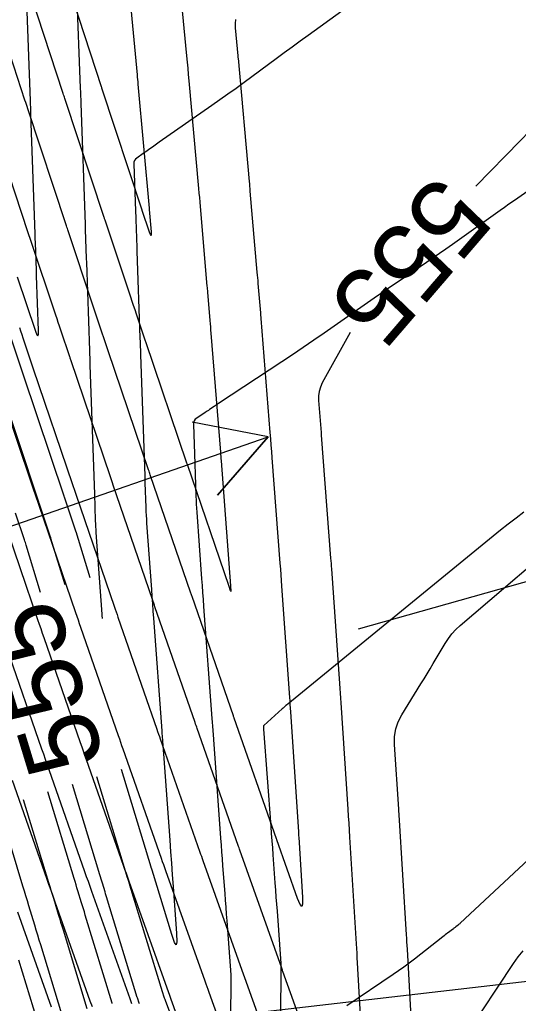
# Model space of a CAD drawing. Extents: x 954385 to 988206, y 1868364 to 1924553.
# Drawn here: x 957830.8 to 957869.5, y 1919489.8 to 1919566.3 of the extents above; entities that cross this region are included whole.
import ezdxf

# ---------------------------------------------------------------- set-up
doc = ezdxf.new("R2010")
doc.units = 0
doc.layers.add('1', color=7, linetype='Continuous')
doc.layers.add('Slopes', color=7, linetype='Continuous')

msp = doc.modelspace()

# ---------------------------------------------------------------- linework, layer by layer
for points in [[(957837.226, 1919519.732), (957837.226, 1919519.741), (957837.209, 1919519.965), (957837.202, 1919520.066), (957836.741, 1919526.42), (957836.726, 1919526.647), (957836.713, 1919526.874), (957836.702, 1919527.101), (957836.694, 1919527.328), (957836.66, 1919528.411), (957836.656, 1919528.551), (957836.652, 1919528.692), (957836.647, 1919528.833), (957836.643, 1919528.973), (957836.626, 1919529.536), (957836.621, 1919529.676), (957836.617, 1919529.817), (957836.612, 1919529.958), (957836.607, 1919530.098), (957836.28, 1919539.427), (957836.27, 1919539.713), (957836.26, 1919539.998), (957836.25, 1919540.284), (957836.24, 1919540.569), (957835.999, 1919547.422), (957835.989, 1919547.727), (957835.91, 1919549.962), (957835.895, 1919550.396), (957835.567, 1919559.766), (957835.557, 1919560.063), (957835.546, 1919560.36), (957835.535, 1919560.657), (957835.524, 1919560.954), (957835.235, 1919568.503)], [(957830.606, 1919546.301), (957832.022, 1919542.079), (957832.135, 1919541.786), (957832.212, 1919541.696), (957832.252, 1919541.808), (957832.256, 1919542.121), (957832.107, 1919546.373), (957832.091, 1919546.824), (957832.018, 1919548.928), (957832.005, 1919549.279), (957831.993, 1919549.629), (957831.667, 1919558.952), (957831.658, 1919559.206), (957831.649, 1919559.46), (957831.64, 1919559.714), (957831.63, 1919559.968), (957831.337, 1919567.616)], [(957855.832, 1919566.952), (957853.223, 1919565.063), (957852.597, 1919564.609), (957851.972, 1919564.153), (957851.348, 1919563.697), (957850.725, 1919563.239), (957848.233, 1919561.405), (957847.609, 1919560.948), (957846.981, 1919560.496), (957846.351, 1919560.048), (957845.718, 1919559.604), (957841.623, 1919556.752), (957841.52, 1919556.68), (957841.417, 1919556.608), (957841.315, 1919556.536), (957841.212, 1919556.463), (957840.804, 1919556.17), (957840.701, 1919556.097), (957840.599, 1919556.025), (957840.496, 1919555.953), (957840.393, 1919555.881), (957839.887, 1919555.53), (957839.784, 1919555.439), (957839.712, 1919555.334), (957839.671, 1919555.213), (957839.66, 1919555.076), (957839.789, 1919551.409), (957839.806, 1919550.915), (957839.812, 1919550.751), (957839.888, 1919548.563), (957839.897, 1919548.299), (957840.134, 1919541.543), (957840.146, 1919541.221), (957840.157, 1919540.899), (957840.168, 1919540.577), (957840.179, 1919540.254), (957840.511, 1919530.802), (957840.513, 1919530.76), (957840.514, 1919530.718), (957840.516, 1919530.675), (957840.517, 1919530.633), (957840.522, 1919530.464), (957840.525, 1919530.379), (957840.528, 1919530.294), (957840.591, 1919528.355), (957840.603, 1919528.053), (957840.617, 1919527.751), (957840.634, 1919527.45), (957840.655, 1919527.148), (957841.029, 1919521.992), (957841.069, 1919521.434), (957841.11, 1919520.876), (957841.15, 1919520.318), (957841.191, 1919519.76), (957841.83, 1919511.001), (957841.845, 1919510.792), (957841.86, 1919510.583), (957841.94, 1919509.494), (957841.959, 1919509.225), (957842.451, 1919502.509), (957842.517, 1919501.609), (957842.583, 1919500.708), (957842.65, 1919499.808), (957842.716, 1919498.908), (957842.986, 1919495.252), (957843.01, 1919494.593), (957842.955, 1919494.361), (957842.82, 1919494.557), (957842.605, 1919495.181), (957841.085, 1919500.166), (957841.062, 1919500.243), (957841.021, 1919500.378), (957841.015, 1919500.397), (957838.7, 1919508.002)], [(957870.876, 1919553.371), (957869.505, 1919552.416), (957869.163, 1919552.176), (957868.821, 1919551.936), (957868.48, 1919551.695), (957868.139, 1919551.454), (957864.419, 1919548.807), (957863.917, 1919548.452), (957863.413, 1919548.1), (957862.908, 1919547.75), (957862.4, 1919547.404), (957860.364, 1919546.023), (957859.856, 1919545.678), (957859.349, 1919545.33), (957858.842, 1919544.981), (957858.337, 1919544.63), (957854.457, 1919541.925), (957853.64, 1919541.359), (957852.82, 1919540.799), (957851.996, 1919540.244), (957851.169, 1919539.694), (957846.243, 1919536.442), (957846.156, 1919536.384), (957846.068, 1919536.326), (957845.981, 1919536.268), (957845.894, 1919536.209), (957845.547, 1919535.973), (957845.46, 1919535.915), (957845.373, 1919535.856), (957845.286, 1919535.798), (957845.198, 1919535.74), (957844.559, 1919535.319), (957844.441, 1919535.221), (957844.359, 1919535.104), (957844.311, 1919534.969), (957844.299, 1919534.816), (957844.407, 1919531.751), (957844.409, 1919531.685), (957844.412, 1919531.618), (957844.414, 1919531.552), (957844.416, 1919531.486), (957844.425, 1919531.221), (957844.427, 1919531.155), (957844.429, 1919531.089), (957844.431, 1919531.022), (957844.434, 1919530.956), (957844.492, 1919529.243), (957844.504, 1919528.936), (957844.519, 1919528.629), (957844.537, 1919528.321), (957844.558, 1919528.014), (957844.934, 1919522.826), (957844.973, 1919522.289), (957845.012, 1919521.753), (957845.051, 1919521.217), (957845.09, 1919520.681), (957845.725, 1919511.97), (957845.747, 1919511.669), (957845.769, 1919511.368), (957845.844, 1919510.35), (957845.846, 1919510.322), (957846.407, 1919502.658), (957846.447, 1919502.122), (957846.486, 1919501.585), (957846.525, 1919501.049), (957846.565, 1919500.513), (957846.723, 1919498.369), (957846.762, 1919497.833), (957846.802, 1919497.297), (957846.841, 1919496.761), (957846.881, 1919496.225), (957847.19, 1919492.023), (957847.193, 1919491.972), (957847.195, 1919491.922), (957847.197, 1919491.871), (957847.197, 1919491.821), (957847.196, 1919491.384), (957847.196, 1919491.339), (957847.195, 1919491.295), (957847.104, 1919482.111)], [(957828.862, 1919545.242), (957830.984, 1919538.91), (957831.066, 1919538.667), (957834.213, 1919529.278), (957834.223, 1919529.247), (957834.239, 1919529.201), (957834.244, 1919529.186), (957835.128, 1919526.546), (957835.133, 1919526.533), (957835.137, 1919526.521), (957835.141, 1919526.508), (957835.145, 1919526.495), (957836.233, 1919522.931)], [(957834.325, 1919522.35), (957833.223, 1919525.96), (957833.204, 1919526.021), (957833.185, 1919526.082), (957833.165, 1919526.142), (957833.145, 1919526.203), (957832.359, 1919528.549), (957832.35, 1919528.576), (957832.341, 1919528.602), (957832.332, 1919528.628), (957832.323, 1919528.655), (957832.287, 1919528.76), (957832.278, 1919528.786), (957832.269, 1919528.812), (957832.26, 1919528.839), (957832.252, 1919528.865), (957829.163, 1919538.081)], [(957832.417, 1919521.768), (957831.301, 1919525.426), (957831.267, 1919525.534), (957831.233, 1919525.643), (957831.198, 1919525.751), (957831.162, 1919525.859), (957830.474, 1919527.912)], [(957869.982, 1919527.989), (957869.373, 1919527.536), (957868.77, 1919527.075), (957868.174, 1919526.606), (957867.583, 1919526.13), (957851.628, 1919513.085), (957851.612, 1919513.072), (957851.596, 1919513.059), (957851.58, 1919513.045), (957851.563, 1919513.032), (957851.474, 1919512.961), (957851.466, 1919512.954), (957851.458, 1919512.947), (957851.426, 1919512.919), (957851.264, 1919512.772), (957851.191, 1919512.706), (957849.765, 1919511.417), (957849.752, 1919511.402), (957849.743, 1919511.386), (957849.738, 1919511.369), (957849.738, 1919511.349), (957849.753, 1919511.14), (957850.308, 1919503.558), (957850.348, 1919503.01), (957850.388, 1919502.463), (957850.429, 1919501.915), (957850.469, 1919501.367), (957850.63, 1919499.177), (957850.67, 1919498.629), (957850.71, 1919498.081), (957850.751, 1919497.534), (957850.791, 1919496.986), (957851.09, 1919492.907), (957851.093, 1919492.859), (957851.095, 1919492.812), (957851.097, 1919492.764), (957851.097, 1919492.717), (957851.095, 1919492.28), (957851.095, 1919492.254), (957851.095, 1919492.229), (957851.095, 1919492.204), (957851.095, 1919492.179), (957851.004, 1919482.966)], [(957878.717, 1919508.807), (957865.032, 1919496.051), (957864.99, 1919496.012), (957864.947, 1919495.975), (957864.903, 1919495.938), (957864.859, 1919495.902), (957864.681, 1919495.76), (957864.637, 1919495.724), (957864.592, 1919495.689), (957864.547, 1919495.655), (957864.501, 1919495.62), (957864.044, 1919495.279), (957863.953, 1919495.21), (957863.862, 1919495.141), (957863.772, 1919495.072), (957863.682, 1919495.001), (957861.468, 1919493.256), (957861.066, 1919492.945), (957860.659, 1919492.642), (957860.246, 1919492.347), (957859.828, 1919492.059), (957856.217, 1919489.626)], [(957845.592, 1919480.76), (957842.124, 1919490.045), (957842.101, 1919490.108), (957842.077, 1919490.171), (957842.054, 1919490.234), (957842.031, 1919490.298), (957841.884, 1919490.701), (957841.88, 1919490.713), (957841.879, 1919490.717), (957839.353, 1919499.006), (957839.326, 1919499.097), (957839.298, 1919499.189), (957839.27, 1919499.28), (957839.242, 1919499.371), (957839.131, 1919499.737), (957839.103, 1919499.828), (957839.075, 1919499.92), (957839.048, 1919500.011), (957839.02, 1919500.103), (957836.792, 1919507.42)], [(957837.982, 1919489.819), (957837.978, 1919489.832), (957837.974, 1919489.844), (957835.89, 1919496.685), (957835.818, 1919496.92), (957835.746, 1919497.156), (957835.674, 1919497.392), (957835.603, 1919497.628), (957835.316, 1919498.571), (957835.244, 1919498.807), (957835.173, 1919499.043), (957835.101, 1919499.278), (957835.029, 1919499.514), (957832.976, 1919506.257)], [(957840.106, 1919489.785), (957840.084, 1919489.844), (957839.938, 1919490.248), (957839.932, 1919490.264), (957839.927, 1919490.28), (957837.622, 1919497.845), (957837.572, 1919498.009), (957837.522, 1919498.172), (957837.472, 1919498.336), (957837.422, 1919498.5), (957837.224, 1919499.154), (957837.174, 1919499.318), (957837.124, 1919499.481), (957837.074, 1919499.645), (957837.025, 1919499.808), (957834.884, 1919506.839)], [(957831.069, 1919505.675), (957833.034, 1919499.22), (957833.128, 1919498.912), (957833.221, 1919498.604), (957833.315, 1919498.296), (957833.409, 1919497.988), (957833.783, 1919496.756), (957833.877, 1919496.448), (957833.97, 1919496.14), (957834.064, 1919495.832), (957834.158, 1919495.524), (957836.022, 1919489.408)], [(957834.069, 1919488.972), (957832.426, 1919494.363), (957832.31, 1919494.743), (957832.195, 1919495.124), (957832.079, 1919495.504), (957831.963, 1919495.884), (957831.501, 1919497.405), (957831.386, 1919497.785), (957831.27, 1919498.165), (957831.154, 1919498.545), (957831.039, 1919498.926), (957829.161, 1919505.094)], [(957830.694, 1919493.203), (957832.117, 1919488.535)]]:
    msp.add_lwpolyline(points)
at = {"layer": '1'}
for points in [[(957842.963, 1919571.847), (957843.758, 1919563.478), (957843.803, 1919562.992), (957843.849, 1919562.505), (957843.893, 1919562.019), (957843.938, 1919561.532), (957844.692, 1919553.16), (957844.723, 1919552.81), (957844.754, 1919552.46), (957844.785, 1919552.109), (957844.815, 1919551.759), (957845.346, 1919545.577), (957845.357, 1919545.459), (957845.367, 1919545.341), (957845.377, 1919545.223), (957845.387, 1919545.104), (957845.571, 1919542.901), (957845.591, 1919542.652), (957845.612, 1919542.403), (957845.632, 1919542.154), (957845.652, 1919541.905), (957846.394, 1919532.673), (957846.408, 1919532.505), (957846.421, 1919532.336), (957846.434, 1919532.168), (957846.447, 1919531.999), (957847.182, 1919522.274), (957847.184, 1919522.243), (957847.209, 1919521.893), (957847.21, 1919521.855), (957847.206, 1919521.841), (957847.197, 1919521.852), (957847.183, 1919521.888), (957847.064, 1919522.232), (957847.063, 1919522.234), (957843.821, 1919531.696), (957843.803, 1919531.749), (957843.785, 1919531.801), (957840.588, 1919541.244), (957840.568, 1919541.303), (957839.867, 1919543.391), (957839.755, 1919543.723), (957839.643, 1919544.056), (957839.532, 1919544.39), (957839.421, 1919544.723), (957837.424, 1919550.703), (957837.406, 1919550.755), (957837.389, 1919550.807), (957837.372, 1919550.859), (957837.355, 1919550.911), (957834.299, 1919560.158), (957834.267, 1919560.253), (957834.236, 1919560.348), (957834.205, 1919560.443), (957834.174, 1919560.538), (957831.197, 1919569.657)], [(957839.055, 1919571.019), (957839.913, 1919561.991), (957839.93, 1919561.81), (957839.947, 1919561.629), (957839.963, 1919561.448), (957839.98, 1919561.268), (957840.847, 1919551.635), (957840.852, 1919551.584), (957840.856, 1919551.533), (957841.006, 1919549.791), (957841.016, 1919549.59), (957840.998, 1919549.519), (957840.954, 1919549.578), (957840.883, 1919549.765), (957840.319, 1919551.456), (957840.314, 1919551.471), (957837.181, 1919560.95), (957837.163, 1919561.005), (957837.145, 1919561.06), (957834.079, 1919570.453)], [(957847.561, 1919566.292), (957847.527, 1919565.979), (957847.537, 1919565.658), (957847.745, 1919563.463), (957847.749, 1919563.422), (957847.753, 1919563.381), (957847.757, 1919563.34), (957847.76, 1919563.299), (957848.624, 1919553.71), (957848.641, 1919553.523), (957848.658, 1919553.335), (957848.674, 1919553.148), (957848.69, 1919552.961), (957849.233, 1919546.647), (957849.251, 1919546.432), (957849.269, 1919546.217), (957849.288, 1919546.002), (957849.306, 1919545.787), (957849.497, 1919543.495), (957849.506, 1919543.387), (957849.515, 1919543.279), (957849.524, 1919543.171), (957849.532, 1919543.064), (957850.245, 1919534.197), (957850.285, 1919533.704), (957850.323, 1919533.212), (957850.361, 1919532.719), (957850.399, 1919532.227), (957851.018, 1919524.026), (957851.052, 1919523.58), (957851.085, 1919523.134), (957851.117, 1919522.688), (957851.149, 1919522.243), (957851.76, 1919513.604), (957851.779, 1919513.325), (957851.799, 1919513.046), (957851.818, 1919512.766), (957851.836, 1919512.487), (957852.451, 1919503.163), (957852.458, 1919503.055), (957852.465, 1919502.946), (957852.472, 1919502.838), (957852.478, 1919502.73), (957852.765, 1919498.045), (957852.772, 1919497.536), (957852.714, 1919497.353), (957852.588, 1919497.498), (957852.396, 1919497.97), (957850.778, 1919502.529), (957850.766, 1919502.565), (957850.753, 1919502.601), (957847.465, 1919511.975), (957847.449, 1919512.02), (957847.433, 1919512.066), (957847.417, 1919512.111), (957847.401, 1919512.157), (957844.186, 1919521.433), (957844.161, 1919521.504), (957844.136, 1919521.575), (957844.112, 1919521.646), (957844.088, 1919521.717), (957840.94, 1919530.904), (957840.908, 1919530.998), (957840.876, 1919531.092), (957840.844, 1919531.186), (957840.812, 1919531.28), (957837.675, 1919540.546), (957837.651, 1919540.617), (957837.627, 1919540.687), (957836.926, 1919542.774), (957836.821, 1919543.087), (957836.716, 1919543.4), (957836.611, 1919543.712), (957836.507, 1919544.025), (957834.529, 1919549.949), (957834.495, 1919550.05), (957834.462, 1919550.15), (957834.429, 1919550.25), (957834.395, 1919550.35), (957831.416, 1919559.366), (957831.362, 1919559.528), (957831.309, 1919559.691), (957831.256, 1919559.854), (957831.203, 1919560.016), (957828.316, 1919568.86)], [(957877.377, 1919566.451), (957872.504, 1919560.096), (957871.839, 1919559.256), (957871.15, 1919558.437), (957870.436, 1919557.639), (957869.697, 1919556.863), (957866.236, 1919553.338)], [(957854.587, 1919482.998), (957851.253, 1919492.286), (957851.23, 1919492.351), (957851.207, 1919492.415), (957851.184, 1919492.48), (957851.161, 1919492.544), (957847.903, 1919501.726), (957847.871, 1919501.817), (957847.839, 1919501.908), (957847.806, 1919501.999), (957847.774, 1919502.091), (957844.588, 1919511.175), (957844.547, 1919511.292), (957844.506, 1919511.409), (957844.465, 1919511.526), (957844.425, 1919511.643), (957841.307, 1919520.636), (957841.258, 1919520.777), (957841.209, 1919520.918), (957841.161, 1919521.059), (957841.112, 1919521.2), (957838.059, 1919530.111), (957838.004, 1919530.273), (957837.949, 1919530.435), (957837.893, 1919530.597), (957837.839, 1919530.759), (957834.761, 1919539.849), (957834.742, 1919539.904), (957834.724, 1919539.96), (957834.705, 1919540.015), (957834.686, 1919540.071), (957833.985, 1919542.158), (957833.887, 1919542.45), (957833.789, 1919542.743), (957833.691, 1919543.035), (957833.593, 1919543.328), (957831.634, 1919549.196), (957831.584, 1919549.345), (957831.535, 1919549.493), (957831.486, 1919549.641), (957831.436, 1919549.79), (957828.534, 1919558.574)], [(957830.771, 1919542.358), (957830.862, 1919542.086), (957830.953, 1919541.814), (957831.044, 1919541.541), (957831.745, 1919539.454), (957831.771, 1919539.379), (957831.796, 1919539.303), (957831.822, 1919539.227), (957831.848, 1919539.152), (957834.865, 1919530.238), (957834.943, 1919530.008), (957835.022, 1919529.778), (957835.1, 1919529.548), (957835.179, 1919529.318), (957838.137, 1919520.683), (957838.21, 1919520.472), (957838.282, 1919520.261), (957838.355, 1919520.05), (957838.428, 1919519.84), (957841.448, 1919511.128), (957841.513, 1919510.94), (957841.579, 1919510.752), (957841.645, 1919510.564), (957841.71, 1919510.376), (957844.796, 1919501.58), (957844.854, 1919501.416), (957844.911, 1919501.251), (957844.969, 1919501.087), (957845.028, 1919500.923), (957848.18, 1919492.04), (957848.23, 1919491.899), (957848.28, 1919491.758), (957848.33, 1919491.618), (957848.381, 1919491.477), (957851.604, 1919482.498)], [(957856.466, 1919541.957), (957854.312, 1919538.046), (957854.162, 1919537.721), (957854.063, 1919537.385), (957854.015, 1919537.038), (957854.019, 1919536.68), (957854.219, 1919534.191), (957854.223, 1919534.139), (957854.227, 1919534.088), (957854.231, 1919534.036), (957854.235, 1919533.985), (957854.957, 1919524.434), (957854.973, 1919524.222), (957854.988, 1919524.01), (957855.004, 1919523.798), (957855.019, 1919523.586), (957855.649, 1919514.676), (957855.675, 1919514.299), (957855.701, 1919513.921), (957855.727, 1919513.544), (957855.752, 1919513.167), (957856.296, 1919504.909), (957856.332, 1919504.366), (957856.367, 1919503.822), (957856.401, 1919503.278), (957856.434, 1919502.735), (957856.941, 1919494.446), (957856.963, 1919494.079), (957856.985, 1919493.712), (957857.006, 1919493.345), (957857.027, 1919492.978), (957857.535, 1919483.964)], [(957848.62, 1919481.998), (957845.508, 1919490.668), (957845.43, 1919490.885), (957845.353, 1919491.102), (957845.276, 1919491.319), (957845.198, 1919491.535), (957842.152, 1919500.12), (957842.068, 1919500.357), (957841.984, 1919500.594), (957841.901, 1919500.832), (957841.817, 1919501.069), (957838.833, 1919509.577), (957838.742, 1919509.836), (957838.652, 1919510.095), (957838.562, 1919510.355), (957838.471, 1919510.614), (957835.549, 1919519.043), (957835.452, 1919519.324), (957835.355, 1919519.604), (957835.259, 1919519.885), (957835.162, 1919520.166), (957832.298, 1919528.525), (957832.196, 1919528.823), (957832.094, 1919529.121), (957831.993, 1919529.419), (957831.892, 1919529.718), (957828.934, 1919538.454)], [(957829.417, 1919527.732), (957832.187, 1919519.648), (957832.307, 1919519.298), (957832.428, 1919518.947), (957832.549, 1919518.597), (957832.67, 1919518.247), (957835.495, 1919510.1), (957835.61, 1919509.769), (957835.725, 1919509.438), (957835.84, 1919509.108), (957835.956, 1919508.777), (957838.839, 1919500.559), (957838.948, 1919500.248), (957839.057, 1919499.938), (957839.167, 1919499.627), (957839.277, 1919499.317), (957842.217, 1919491.031), (957842.321, 1919490.738), (957842.426, 1919490.445), (957842.53, 1919490.152), (957842.635, 1919489.859), (957845.637, 1919481.497)], [(957861.406, 1919485.395), (957860.921, 1919494.018), (957860.905, 1919494.303), (957860.888, 1919494.588), (957860.871, 1919494.873), (957860.854, 1919495.157), (957860.284, 1919504.479), (957860.278, 1919504.588), (957860.271, 1919504.698), (957860.264, 1919504.808), (957860.256, 1919504.917), (957859.925, 1919509.951), (957859.93, 1919510.561), (957860.027, 1919511.149), (957860.216, 1919511.714), (957860.497, 1919512.255), (957861.978, 1919514.658), (957862.218, 1919515.048), (957862.456, 1919515.44), (957862.693, 1919515.832), (957862.928, 1919516.225), (957863.865, 1919517.8), (957864.113, 1919518.182), (957864.39, 1919518.539), (957864.695, 1919518.873), (957865.029, 1919519.183), (957874.071, 1919526.91)], [(957839.499, 1919489.788), (957839.367, 1919490.157), (957839.236, 1919490.527), (957836.402, 1919498.514), (957836.266, 1919498.897), (957836.13, 1919499.281), (957835.995, 1919499.664), (957835.86, 1919500.048), (957833.079, 1919507.978), (957832.938, 1919508.38), (957832.798, 1919508.782), (957832.658, 1919509.183), (957832.518, 1919509.586), (957829.792, 1919517.45)], [(957830.201, 1919507.179), (957832.882, 1919499.538), (957833.042, 1919499.081), (957833.203, 1919498.624), (957833.364, 1919498.167), (957833.526, 1919497.711), (957836.254, 1919490.022), (957836.413, 1919489.577)], [(957833.273, 1919489.518), (957830.651, 1919496.908)], [(957865.466, 1919487.324), (957869.16, 1919492.925), (957869.526, 1919493.436), (957869.929, 1919493.912)]]:
    msp.add_lwpolyline(points, dxfattribs=at)
at = {"layer": 'Slopes'}
for points in [[(957857.131, 1919518.928), (957989.451, 1919556.257), (957985.265, 1919551.959), (957989.451, 1919556.257), (957983.636, 1919557.733)], [(957807.131, 1919518.928), (957850.097, 1919533.856), (957846.174, 1919529.317), (957850.097, 1919533.856), (957844.204, 1919534.985)], [(958107.131, 1919518.928), (957780.867, 1919481.187), (957785.684, 1919484.764), (957780.867, 1919481.187), (957786.373, 1919478.804)]]:
    msp.add_lwpolyline(points, dxfattribs=at)

# ---------------------------------------------------------------- texts
msp.add_text('555', height=6, rotation=106.95557).set_placement((957837.441, 1919508.738))
at = {"layer": '1'}
msp.add_text('555', height=6, rotation=229.33945, dxfattribs=at).set_placement((957863.261, 1919554.481))

doc.saveas('drawing.dxf')
